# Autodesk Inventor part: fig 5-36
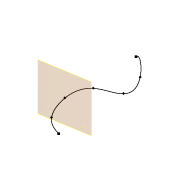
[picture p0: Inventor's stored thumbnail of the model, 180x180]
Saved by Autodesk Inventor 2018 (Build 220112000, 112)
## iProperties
Created: 2010-02
Part Number: fig 5-36
Document SubType Name: Modeling
Designer: CADSoft
Density: 1 g/cm^3
Material: Generic
Appearance: Default
Author: CADSoft
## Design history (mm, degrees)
sketch "Sketch1"
  geometry: 8 further points
  constraints: 8 other
workplane "Work Plane1"
workplane "Work Plane2"
